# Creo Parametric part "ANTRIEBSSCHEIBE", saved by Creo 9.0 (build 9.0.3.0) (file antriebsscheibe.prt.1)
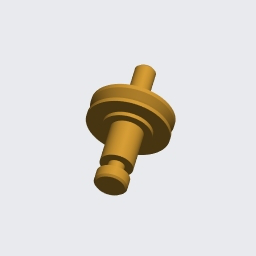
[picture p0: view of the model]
Units: millimeter Kilogram Sec (mmKs); MM, KILOGRAM, SECS
Materials in the file: STAHL

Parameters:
  WERKSTOFF = "Stahl"
  ERSTELLER = "ARINDA"
  BENENNUNG = "XXX"
  TEILETYP = "K"
  PTC_MASTER_MATERIAL = "STAHL"
  CLASS = "h"
  PLACEMENT = "EXTERNAL"

Other parameters: MASSE, MINOR_DIAMETER, PITCH

Created from: ARINDA_STARTTEIL.PRT

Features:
  1. coordinate system
  2. datum plane "RECHTS_Y-Z"
  3. datum plane "OBEN_X-Z"
  4. datum plane "VORNE_X-Y"
  5. datum axis
  6. datum axis
  7. datum axis
  8. datum point "PNT0"
  9. revolve "Drehen 1"
  10. revolved cut "Drehen 2"
  11. revolved cut "Drehen 3"
  12. chamfer "Fase 2"
  13. datum plane "DTM1"
  14. feature "Kosmetisches Gewinde 1"
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
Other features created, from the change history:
  coordinate system "CS1"
  chamfer "Fase 1"
  datum plane "DTM1"
  extrusion "Profil 1"

Other named items: WELLE, RIEMEN, FIXIERUNG, F0_5, GEWINDE, LOGO, A_X, A_Y, A_Z, CS0

Layers: 01_ACHSEN_STD, 01_EBENEN, 01_EBENEN_STD, 01_KOORDSYS_STD, 01_PUNKTE_STD, GEWINDE, SAMMELFLÄCHEN, VOLUMENGEOMETRIE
